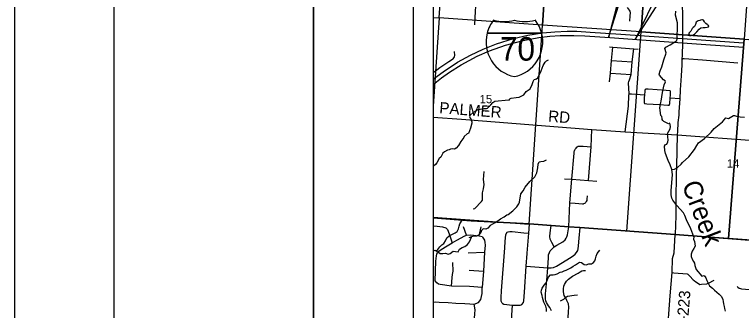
# Model space of a CAD drawing. Extents: x 0 to 34, y 0 to 22.
# Drawn here: x 0 to 3.646, y 15.479 to 16.964 of the extents above; entities that cross this region are included whole.
import ezdxf

# ---------------------------------------------------------------- set-up
doc = ezdxf.new("R2010")
doc.units = 0
for name, color, linetype in [('GM_X_Corporation', 7, 'Continuous'), ('GM_X_County_Road', 7, 'Continuous'), ('GM_X_Interstate_Location', 7, 'Continuous'), ('GM_X_Interstate_Route', 7, 'Continuous'), ('GM_X_Interstate_Shield', 7, 'Continuous'), ('GM_X_Minor_Lake', 7, 'Continuous'), ('GM_X_Minor_River', 7, 'Continuous'), ('GM_X_Minor_River_Text', 7, 'Continuous'), ('GM_X_Section', 7, 'Continuous'), ('GM_X_Section_Text', 7, 'Continuous'), ('GM_X_Township_Road', 7, 'Continuous'), ('GM_X_Township_Road_Text', 7, 'Continuous'), ('GM_X_Unincorporated_Text', 7, 'Continuous'), ('SH_Border', 7, 'Continuous'), ('SH_Cut_Line', 7, 'Continuous'), ('SH_Data', 7, 'Continuous'), ('SH_Text', 7, 'Continuous')]:
    doc.layers.add(name, color=color, linetype=linetype)

msp = doc.modelspace()

# ---------------------------------------------------------------- linework, layer by layer
at = {"layer": 'GM_X_Corporation'}
msp.add_lwpolyline([(4.6285, 18.3373), (3.4218, 18.4152), (2.5696, 18.468), (2.2415, 18.4869), (2.1111, 18.4924), (2.1, 18.4929), (2.1, 15.9442), (2.2903, 15.9292), (2.5827, 15.9132), (2.6921, 15.9056), (2.7799, 15.8989), (2.8362, 15.8952), (3.3132, 15.8609), (3.9945, 15.8088)], dxfattribs=at)
msp.add_lwpolyline([(2.1, 15.9442), (2.1, 14.1), (4.9875, 14.1), (5.0611, 15.2147), (5.0952, 15.7318), (4.92, 15.7429), (4.5905, 15.7634), (4.2803, 15.787), (3.9945, 15.8088), (3.3132, 15.8609), (2.8362, 15.8952), (2.7799, 15.8989), (2.6921, 15.9056), (2.5827, 15.9132), (2.2903, 15.9292)], close=True, dxfattribs=at)
at = {"layer": 'GM_X_County_Road'}
msp.add_lwpolyline([(3.349, 17.0196), (3.3501, 16.9565), (3.351, 16.892), (3.3504, 16.8597), (3.3501, 16.8435), (3.3497, 16.8226), (3.3492, 16.761), (3.348, 16.7399), (3.3465, 16.7111), (3.3435, 16.6573), (3.3392, 16.5869), (3.3367, 16.5406), (3.3323, 16.4753), (3.3313, 16.4588), (3.3278, 16.4229), (3.3248, 16.377), (3.3231, 16.3603), (3.3199, 16.2036), (3.3191, 16.1601), (3.3171, 16.0367), (3.3167, 15.9539), (3.3134, 15.8604)], dxfattribs=at)
at = {"layer": 'GM_X_Interstate_Route'}
for points in [[(2.1, 16.639), (2.113, 16.6494), (2.1561, 16.681), (2.1894, 16.7035), (2.2223, 16.7246), (2.2873, 16.7603), (2.3511, 16.7903), (2.4179, 16.8166), (2.5032, 16.8433), (2.5746, 16.8602), (2.6489, 16.872), (2.7093, 16.8775), (2.7713, 16.8804), (2.82, 16.8799), (2.8875, 16.8762), (3.041, 16.8655), (3.3501, 16.8435), (3.6568, 16.822)], [(2.1, 16.6134), (2.1421, 16.6469), (2.1819, 16.6747), (2.2396, 16.7115), (2.3206, 16.7545), (2.382, 16.7818), (2.4619, 16.8103), (2.5513, 16.8342), (2.6306, 16.8491), (2.6852, 16.8555), (2.7373, 16.8587), (2.8057, 16.8596), (2.8611, 16.8581), (2.9866, 16.849), (3.1453, 16.8368), (3.3497, 16.8226), (3.6565, 16.8011)]]:
    msp.add_lwpolyline(points, dxfattribs=at)
at = {"layer": 'GM_X_Interstate_Shield'}
for p, q in [((2.3707, 16.8702), (2.644, 16.8702)), ((2.644, 16.8702), (2.3707, 16.8702)), ((2.644, 16.8702), (2.3707, 16.8702))]:
    msp.add_line(p, q, dxfattribs=at)
for centre, start, end in [((2.5428, 16.8267), 141.669, 165.8066), ((2.4554, 17.1066), 253.0091, 286.9909), ((2.5592, 17.1066), 253.0091, 286.9909), ((2.4718, 16.8267), 14.1934, 38.331), ((2.5428, 16.8267), 165.8066, 258.463), ((2.4718, 16.8267), 281.537, 14.1934)]:
    msp.add_arc(centre, 0.1776, start, end, dxfattribs=at)
at = {"layer": 'GM_X_Minor_Lake'}
for points in [[(3.482, 16.9081), (3.4782, 16.9104), (3.4741, 16.9142), (3.4676, 16.9195), (3.4627, 16.9249), (3.4601, 16.9275), (3.4552, 16.9363), (3.4502, 16.9378), (3.4472, 16.9374), (3.4408, 16.9352), (3.4374, 16.9344), (3.4294, 16.9318), (3.4199, 16.9253), (3.415, 16.9136), (3.4108, 16.9045), (3.4047, 16.8988), (3.3983, 16.8935), (3.3929, 16.881), (3.3842, 16.8727), (3.3812, 16.8681)], [(3.3812, 16.8681), (3.3861, 16.8594), (3.3937, 16.8586), (3.3997, 16.8601), (3.4065, 16.862), (3.4126, 16.8673), (3.4179, 16.8722), (3.4217, 16.8767), (3.4346, 16.8908), (3.4426, 16.8972), (3.4543, 16.8991), (3.4646, 16.8987), (3.4744, 16.9005), (3.4805, 16.9024), (3.482, 16.9081)]]:
    msp.add_lwpolyline(points, dxfattribs=at)
at = {"layer": 'GM_X_Minor_River'}
for points in [[(3.4074, 15.8485), (3.392, 15.8893), (3.3698, 15.9345), (3.3626, 15.9562), (3.3562, 15.9683), (3.3219, 16.0064), (3.3018, 16.0322), (3.2973, 16.0425), (3.2936, 16.0588), (3.2944, 16.0797), (3.3002, 16.1617), (3.2969, 16.186), (3.289, 16.2104), (3.2784, 16.2324), (3.266, 16.2674), (3.2622, 16.2826), (3.26, 16.3035), (3.2653, 16.3114), (3.2721, 16.3144), (3.2774, 16.3251), (3.279, 16.3334), (3.2756, 16.3672), (3.2882, 16.39), (3.2905, 16.4017), (3.2875, 16.4196), (3.2807, 16.4162), (3.2565, 16.4272), (3.2512, 16.4318), (3.2481, 16.4379), (3.2485, 16.4428), (3.2463, 16.4519), (3.2417, 16.458), (3.2361, 16.4952), (3.2423, 16.5222), (3.2438, 16.5286), (3.2503, 16.5734), (3.2591, 16.611), (3.2648, 16.6258), (3.2644, 16.6311), (3.2554, 16.6368), (3.2357, 16.6593), (3.2342, 16.665), (3.2384, 16.6824), (3.2476, 16.7025), (3.2563, 16.7363), (3.2582, 16.7427), (3.2674, 16.7659), (3.2678, 16.7727), (3.2614, 16.7936), (3.2667, 16.8008), (3.2883, 16.8118), (3.3065, 16.8231), (3.3213, 16.8337), (3.3243, 16.842), (3.3256, 16.9089), (3.3249, 16.9225), (3.3151, 16.9616), (3.317, 16.9806)], [(2.3019, 16.4734), (2.325, 16.487), (2.3538, 16.4919), (2.3678, 16.4919), (2.3731, 16.4945), (2.3891, 16.5108), (2.3986, 16.5229), (2.4096, 16.529), (2.4785, 16.5357), (2.4834, 16.5368), (2.4868, 16.5425), (2.4918, 16.5448), (2.5164, 16.547), (2.5312, 16.5488), (2.5543, 16.5609), (2.5668, 16.578), (2.5862, 16.592), (2.5968, 16.6136), (2.601, 16.628), (2.6067, 16.6379), (2.6128, 16.6402), (2.6177, 16.6409), (2.6249, 16.6473), (2.6416, 16.6811), (2.6515, 16.7084), (2.661, 16.7251), (2.6679, 16.7315), (2.6777, 16.7364)], [(2.3019, 16.4734), (2.2844, 16.4581), (2.2825, 16.4524), (2.2848, 16.4441), (2.2901, 16.4376), (2.2935, 16.4262), (2.2938, 16.4198), (2.2874, 16.394), (2.2763, 16.3667), (2.2703, 16.3655), (2.2555, 16.3523), (2.2536, 16.3469), (2.2385, 16.3276), (2.2275, 16.3067), (2.2153, 16.2935), (2.2066, 16.2889), (2.1972, 16.2908), (2.187, 16.2889), (2.1805, 16.2852), (2.1714, 16.2829), (2.1559, 16.2746), (2.148, 16.2685), (2.1385, 16.2491), (2.1294, 16.2423), (2.1184, 16.2199), (2.1112, 16.2108), (2.1, 16.201)], [(3.2961, 16.1884), (3.2976, 16.1868), (3.3112, 16.1875), (3.326, 16.1962), (3.3442, 16.2137), (3.3503, 16.2216), (3.3822, 16.2496), (3.4114, 16.2864), (3.4221, 16.3069), (3.4316, 16.3198), (3.4615, 16.3417), (3.4949, 16.3735), (3.5093, 16.3925), (3.5507, 16.4258), (3.5685, 16.4451), (3.5806, 16.4432), (3.6057, 16.458), (3.6121, 16.4576), (3.6208, 16.4537), (3.6401, 16.4503), (3.6613, 16.4491)], [(2.4119, 15.9202), (2.4379, 15.9385), (2.4561, 15.9483), (2.4701, 15.9593), (2.4758, 15.9612), (2.4993, 15.9794), (2.5198, 15.9994), (2.5301, 16.0142), (2.5323, 16.0222), (2.5404, 16.0647), (2.5514, 16.0799), (2.5617, 16.0985), (2.5848, 16.1261), (2.6095, 16.1504), (2.6156, 16.1591), (2.6197, 16.1701), (2.6243, 16.1955), (2.6259, 16.2138), (2.6308, 16.2248), (2.6403, 16.2262), (2.6555, 16.2285), (2.6687, 16.2353)], [(2.3005, 15.9885), (2.3089, 15.9912), (2.3419, 16.0253), (2.3468, 16.0321), (2.348, 16.0431), (2.3473, 16.0686), (2.3522, 16.0887), (2.3549, 16.1111), (2.3531, 16.1365), (2.3554, 16.1764)], [(2.1155, 15.7789), (2.1225, 15.7855), (2.1329, 15.7975), (2.1429, 15.8091), (2.1532, 15.815), (2.1617, 15.829), (2.1676, 15.8437), (2.1806, 15.853), (2.1909, 15.8586), (2.2008, 15.8634), (2.2104, 15.8685), (2.2199, 15.8752), (2.2277, 15.888), (2.2298, 15.9021), (2.2333, 15.9134), (2.2448, 15.9322)], [(2.4119, 15.9202), (2.3975, 15.9117), (2.3857, 15.9057), (2.3738, 15.8914), (2.3639, 15.8874), (2.351, 15.8879), (2.3415, 15.8811), (2.3391, 15.8705), (2.3276, 15.8566), (2.3177, 15.8525), (2.3044, 15.8519), (2.2915, 15.849), (2.2786, 15.8431)], [(2.1, 15.7776), (2.1012, 15.7789), (2.1107, 15.7822), (2.1231, 15.7737), (2.1351, 15.7644), (2.1487, 15.7642), (2.162, 15.7663), (2.1748, 15.7612), (2.1858, 15.7656), (2.2004, 15.7772), (2.2121, 15.7755), (2.2245, 15.7738), (2.2319, 15.787), (2.246, 15.7948), (2.2586, 15.8007), (2.2724, 15.81), (2.2816, 15.8235), (2.2867, 15.8345), (2.2922, 15.8469)], [(3.4074, 15.8485), (3.4059, 15.837), (3.4103, 15.8248), (3.412, 15.8134), (3.4134, 15.802), (3.4076, 15.7892), (3.3991, 15.7763), (3.3933, 15.7616), (3.3935, 15.7491), (3.3998, 15.7361), (3.4058, 15.7254), (3.4099, 15.7159), (3.4131, 15.7041), (3.4153, 15.6942), (3.419, 15.6846), (3.4283, 15.6735), (3.4369, 15.6636), (3.4474, 15.6513), (3.4599, 15.6538), (3.467, 15.6431), (3.4726, 15.6298), (3.4788, 15.6153), (3.4867, 15.6031), (3.5017, 15.5911), (3.5114, 15.5816), (3.5351, 15.56), (3.5459, 15.5485), (3.553, 15.5348), (3.5548, 15.5234), (3.5554, 15.5124), (3.5587, 15.4987), (3.5608, 15.4888), (3.5641, 15.4755)], [(2.6682, 15.4734), (2.6679, 15.4867), (2.6658, 15.5), (2.6554, 15.5214), (2.651, 15.5317), (2.6489, 15.5442), (2.6474, 15.5541), (2.6419, 15.5701), (2.6432, 15.5815), (2.6471, 15.5913), (2.6563, 15.6056), (2.6663, 15.6184), (2.6729, 15.6339), (2.6776, 15.6468), (2.688, 15.6585), (2.702, 15.6572), (2.7118, 15.659), (2.7214, 15.663), (2.7377, 15.6705), (2.7476, 15.6734), (2.7571, 15.6771), (2.767, 15.6816), (2.7803, 15.6875), (2.7899, 15.6927), (2.8021, 15.7013), (2.8131, 15.7084), (2.8238, 15.7155), (2.8341, 15.7207), (2.8443, 15.7191), (2.8575, 15.7091), (2.8677, 15.7075), (2.8802, 15.7127), (2.8939, 15.7129), (2.9042, 15.7189), (2.9103, 15.7287), (2.9139, 15.7389), (2.9174, 15.7514), (2.9228, 15.7646), (2.9351, 15.7808)]]:
    msp.add_lwpolyline(points, dxfattribs=at)
at = {"layer": 'GM_X_Section'}
for points in [[(2.1995, 17.9442), (2.7132, 17.9071), (2.648, 16.9108), (2.1294, 16.9473)], [(2.7132, 17.9071), (3.2112, 17.8728), (3.1425, 16.8774), (2.648, 16.9108)], [(3.2112, 17.8728), (3.7302, 17.8352), (3.6598, 16.8406), (3.1425, 16.8774)], [(3.1425, 16.8774), (3.6598, 16.8406), (3.5815, 15.8402), (3.0715, 15.8772)], [(3.6598, 16.8406), (4.1558, 16.8052), (4.0871, 15.8035), (3.5815, 15.8402)]]:
    msp.add_lwpolyline(points, close=True, dxfattribs=at)
at = {"layer": 'GM_X_Township_Road'}
for p, q in [((2.9948, 16.7342), (3.0977, 16.7263)), ((2.9893, 16.6696), (3.0926, 16.6628)), ((3.3231, 16.3603), (4.6218, 16.2647)), ((2.2673, 15.8569), (2.2518, 15.8991)), ((2.3307, 15.8532), (2.3414, 15.8986)), ((2.2762, 15.7687), (2.3578, 15.7712)), ((2.2801, 15.6809), (2.3526, 15.677))]:
    msp.add_line(p, q, dxfattribs=at)
for points in [[(2.3085, 16.9122), (2.3125, 16.9811), (2.3163, 17.0281), (2.3193, 17.067), (2.3194, 17.0755), (2.3174, 17.0843), (2.311, 17.0972), (2.3049, 17.107), (2.2944, 17.1229), (2.2875, 17.1329), (2.2826, 17.1425), (2.2798, 17.1494), (2.277, 17.1627), (2.2761, 17.1713), (2.2765, 17.1877), (2.2769, 17.1956)], [(3.0855, 16.9316), (3.0885, 16.9576), (3.0891, 16.973), (3.0874, 16.9807), (3.0839, 16.9866), (3.0744, 16.9992)], [(2.1, 16.6729), (2.1187, 16.6873), (2.1332, 16.6985), (2.1534, 16.7119), (2.1782, 16.7287), (2.1961, 16.7398), (2.1996, 16.7424), (2.2034, 16.7473), (2.2065, 16.7514), (2.2077, 16.7579), (2.2069, 16.7792)], [(2.9842, 16.8017), (3.0005, 16.8003), (3.1063, 16.7926), (3.1288, 16.791)], [(2.985, 16.6263), (2.9893, 16.6696), (2.9948, 16.7342), (3.0005, 16.8003)], [(3.0793, 16.506), (3.0814, 16.5586), (3.0826, 16.5662), (3.0791, 16.6213), (3.0818, 16.6274), (3.0848, 16.6369), (3.0926, 16.6628), (3.0977, 16.7263), (3.1063, 16.7926)], [(3.348, 16.7399), (3.3516, 16.7424), (3.3546, 16.7435), (3.3584, 16.744), (3.4509, 16.7375), (3.6276, 16.7217)], [(3.0826, 16.5662), (3.0945, 16.5659), (3.1598, 16.5618)], [(3.3367, 16.5406), (3.289, 16.545), (3.2899, 16.5607), (3.2908, 16.5751), (3.2904, 16.5784), (3.2893, 16.581), (3.2862, 16.5821), (3.2684, 16.5832), (3.1778, 16.5895), (3.1718, 16.5892), (3.1664, 16.5892), (3.1628, 16.5875), (3.162, 16.5832), (3.1615, 16.5771), (3.1598, 16.5618), (3.1586, 16.5453), (3.1581, 16.5326), (3.1579, 16.5263), (3.1577, 16.5215), (3.1596, 16.5183), (3.1632, 16.5173), (3.1708, 16.5168), (3.2356, 16.5122), (3.2775, 16.5089), (3.2833, 16.5092), (3.2852, 16.511), (3.2859, 16.5133), (3.2864, 16.5179), (3.289, 16.545)], [(3.0631, 16.3758), (3.0792, 16.504), (3.0793, 16.506)], [(2.1, 16.4486), (2.2422, 16.4389), (2.8964, 16.3876), (3.0631, 16.3758), (3.3231, 16.3603)], [(2.8792, 16.1312), (2.8919, 16.3002), (2.8964, 16.3876)], [(2.7801, 15.8984), (2.786, 16.0188), (2.7957, 16.1373), (2.8066, 16.2691), (2.8073, 16.2733), (2.8077, 16.2763), (2.8088, 16.2797), (2.8103, 16.285), (2.8122, 16.2889), (2.8148, 16.2919), (2.8167, 16.2942), (2.8197, 16.298), (2.8224, 16.3003), (2.8266, 16.303), (2.8326, 16.3034), (2.8364, 16.3034), (2.8414, 16.3034), (2.8524, 16.3031), (2.8919, 16.3002)], [(2.7582, 16.14), (2.7957, 16.1373), (2.8792, 16.1312), (2.9207, 16.1282)], [(2.786, 16.0188), (2.8128, 16.0174), (2.8488, 16.0148), (2.8534, 16.0145), (2.8564, 16.0153), (2.8598, 16.0168), (2.8636, 16.0195), (2.8663, 16.0225), (2.8693, 16.0263), (2.8716, 16.0309), (2.8731, 16.0378), (2.8746, 16.0541)], [(2.1, 15.9029), (2.1192, 15.9018), (2.1466, 15.8989), (2.1629, 15.8938), (2.171, 15.8849), (2.1804, 15.8629), (2.1952, 15.8185)], [(2.545, 15.5091), (2.5522, 15.5184), (2.5554, 15.5278), (2.5578, 15.5702), (2.5664, 15.7006), (2.5717, 15.7647), (2.5718, 15.767), (2.5793, 15.8664), (2.5829, 15.9126)], [(2.6937, 15.4767), (2.6858, 15.4931), (2.679, 15.5026), (2.6675, 15.5193), (2.6647, 15.5281), (2.6639, 15.5373), (2.6639, 15.5624), (2.6694, 15.6298), (2.6747, 15.6929), (2.678, 15.7435), (2.6788, 15.7582), (2.6828, 15.7698), (2.6871, 15.7783), (2.6962, 15.7891), (2.7075, 15.799), (2.7209, 15.8068), (2.7495, 15.8233), (2.7614, 15.8333), (2.7666, 15.841), (2.7709, 15.848), (2.7739, 15.8583), (2.7801, 15.8984)], [(2.7075, 15.799), (2.6949, 15.8198), (2.691, 15.826), (2.6864, 15.8367), (2.6849, 15.8501), (2.6871, 15.8684), (2.6923, 15.9051)], [(2.4639, 15.8597), (2.4715, 15.8712), (2.4757, 15.8738), (2.4841, 15.8756), (2.4969, 15.875), (2.555, 15.8687), (2.5793, 15.8664)], [(2.5664, 15.7006), (2.6533, 15.6945), (2.6747, 15.6929), (2.6918, 15.6925), (2.7039, 15.6945), (2.719, 15.7014), (2.7479, 15.7201), (2.7834, 15.7418), (2.8018, 15.7536), (2.8118, 15.7622), (2.8185, 15.7691), (2.8224, 15.7744), (2.8255, 15.7804), (2.8278, 15.7878), (2.8295, 15.8033), (2.8327, 15.8422), (2.8365, 15.8947)], [(2.3457, 15.5936), (2.2827, 15.5994), (2.1925, 15.6001), (2.1352, 15.6093), (2.1269, 15.6113), (2.1178, 15.6178), (2.1099, 15.6285), (2.1124, 15.7266), (2.116, 15.7524), (2.1175, 15.7612), (2.1221, 15.7692), (2.1279, 15.7763), (2.1351, 15.7809), (2.1622, 15.7975), (2.1952, 15.8185), (2.2181, 15.8318), (2.241, 15.8442), (2.2555, 15.8525), (2.2673, 15.8569), (2.287, 15.858), (2.3307, 15.8532), (2.345, 15.8505), (2.348, 15.847), (2.3514, 15.8417), (2.3566, 15.8318), (2.3585, 15.8203), (2.3599, 15.8074), (2.3578, 15.7712), (2.3526, 15.677), (2.3457, 15.5936)], [(2.4466, 15.5158), (2.4407, 15.5262), (2.4407, 15.5435), (2.4431, 15.5777), (2.4585, 15.7929), (2.461, 15.8254), (2.4639, 15.8597)], [(3.2738, 15.3489), (3.2886, 15.5518), (3.2988, 15.6689), (3.3006, 15.7403), (3.3081, 15.7684), (3.3134, 15.8604)], [(2.1925, 15.6001), (2.1946, 15.6441), (2.1974, 15.6595), (2.2002, 15.6762), (2.1992, 15.7204)], [(2.7736, 15.3839), (2.7785, 15.4716), (2.7797, 15.495), (2.7781, 15.5118), (2.7706, 15.5297), (2.763, 15.544), (2.7574, 15.554), (2.7532, 15.5733), (2.7535, 15.5877), (2.7558, 15.6012), (2.7588, 15.6087), (2.7686, 15.6255), (2.7788, 15.6363), (2.7992, 15.6505), (2.8265, 15.6666), (2.8378, 15.6731), (2.8462, 15.6774), (2.8539, 15.679), (2.8641, 15.6796)], [(3.2988, 15.6689), (3.3072, 15.6682), (3.3742, 15.662), (3.3772, 15.6618), (3.3866, 15.6517), (3.4039, 15.6334), (3.4082, 15.6289), (3.417, 15.623), (3.431, 15.6136), (3.4373, 15.6094), (3.4465, 15.6103), (3.4716, 15.6128), (3.4734, 15.613), (3.4869, 15.6195), (3.502, 15.6269), (3.5096, 15.6306)], [(2.1, 15.5213), (2.1123, 15.5221), (2.1299, 15.5208), (2.1752, 15.5186), (2.2143, 15.5164), (2.259, 15.5135), (2.2841, 15.5119), (2.3051, 15.5103), (2.3272, 15.5184), (2.339, 15.5332), (2.3454, 15.5645), (2.3457, 15.5936)], [(3.6242, 15.5996), (3.6285, 15.5952), (3.634, 15.5916), (3.6407, 15.5888), (3.6457, 15.5875), (3.6859, 15.5845)], [(2.7379, 15.5281), (2.7551, 15.5361), (2.763, 15.544), (2.7738, 15.55), (2.8076, 15.5556), (2.8243, 15.5576)], [(2.3057, 15.4178), (2.3089, 15.4623), (2.3099, 15.4817), (2.3051, 15.5103)], [(2.4466, 15.5158), (2.4548, 15.5102), (2.4981, 15.5056), (2.5367, 15.5048), (2.541, 15.5064), (2.545, 15.5091)], [(2.4938, 15.4041), (2.4951, 15.456), (2.4981, 15.5056)]]:
    msp.add_lwpolyline(points, dxfattribs=at)
at = {"layer": 'GM_X_Unincorporated_Text'}
for points in [[(2.1, 17.9509), (2.1, 16.9493), (2.1294, 16.9473), (2.1995, 17.9442)], [(2.1, 16.5043), (2.1, 15.9477), (2.5814, 15.9129), (2.648, 16.9108), (2.1294, 16.9473)]]:
    msp.add_lwpolyline(points, close=True, dxfattribs=at)
at = {"layer": 'SH_Border'}
for points in [[(0.5, 21.5), (1.5, 21.5), (1.5, 0.5), (0.5, 0.5)], [(1.5, 21.5), (33.5, 21.5), (33.5, 0.5), (1.5, 0.5)]]:
    msp.add_lwpolyline(points, close=True, dxfattribs=at)
at = {"layer": 'SH_Cut_Line'}
for points in [[(0, 0), (34, 0), (34, 22), (0, 22)], [(8.9, 15.4827), (8.9, 20.9), (2.1, 20.9), (2.1, 15.9442), (2.2903, 15.9292), (2.5827, 15.9132), (2.6921, 15.9056), (2.7799, 15.8989), (2.8362, 15.8952), (3.3132, 15.8609), (3.9945, 15.8088), (4.2803, 15.787), (4.5905, 15.7634), (4.92, 15.7429), (5.0952, 15.7318), (5.9419, 15.6782), (6.1109, 15.6683), (6.4, 15.6498), (6.624, 15.6351), (6.838, 15.6206), (7.6503, 15.5653), (8.6741, 15.4976)], [(2.1, 15.9442), (2.1, 14.1), (8.9, 14.1), (8.9, 15.4827), (8.6741, 15.4976), (7.6503, 15.5653), (6.838, 15.6206), (6.624, 15.6351), (6.4, 15.6498), (6.1109, 15.6683), (5.9419, 15.6782), (5.0952, 15.7318), (4.92, 15.7429), (4.5905, 15.7634), (4.2803, 15.787), (3.9945, 15.8088), (3.3132, 15.8609), (2.8362, 15.8952), (2.7799, 15.8989), (2.6921, 15.9056), (2.5827, 15.9132), (2.2903, 15.9292)]]:
    msp.add_lwpolyline(points, close=True, dxfattribs=at)
at = {"layer": 'SH_Data'}
msp.add_line((2, 21), (2, 14), dxfattribs=at)
at = {"layer": 'SH_Text'}
for points in [[(2.98, 16.8495), (3.6186, 18.8742), (3.6186, 19.301)], [(3.1124, 16.8393), (3.9683, 18.1701), (3.9683, 18.5968)]]:
    msp.add_lwpolyline(points, close=True, dxfattribs=at)

# ---------------------------------------------------------------- texts
at = {"layer": 'GM_X_Interstate_Location'}
for s in ['-', '.', ',']:
    msp.add_text(s, height=0.000189, dxfattribs=at).set_placement((2.5073, 16.7947))
msp.add_text('70', height=0.000189, rotation=0, dxfattribs=at).set_placement((2.4686, 16.7555))
at = {"layer": 'GM_X_Interstate_Shield'}
msp.add_text('70', height=0.11837, dxfattribs=at).set_placement((2.4346, 16.7326))
at = {"layer": 'GM_X_Minor_River_Text'}
msp.add_text('Creek', height=0.09472, rotation=290.9911, dxfattribs=at).set_placement((3.3458, 16.1101))
at = {"layer": 'GM_X_Section_Text'}
for s, p in [('15', (2.3332, 16.5191)), ('14', (3.5736, 16.196))]:
    msp.add_text(s, height=0.04186, rotation=0, dxfattribs=at).set_placement(p)
at = {"layer": 'GM_X_Township_Road_Text'}
for s, rotation, p in [('PALMER', 355.7569, (2.1293, 16.4685)), ('RD', 355.5623, (2.6753, 16.4268)), ('T-223', 85.4937, (3.3752, 15.379))]:
    msp.add_text(s, height=0.05682, rotation=rotation, dxfattribs=at).set_placement(p)

doc.saveas('drawing.dxf')
